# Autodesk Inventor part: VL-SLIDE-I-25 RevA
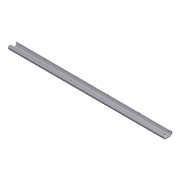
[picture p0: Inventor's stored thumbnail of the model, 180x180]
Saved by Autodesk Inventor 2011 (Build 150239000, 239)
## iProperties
Created: 2007-09
Part Number: VL-SLIDE-I-25 RevA
Material: Stainless Steel, Austenitic
Document SubType Name: Modeling
Density: 8.03 g/cm^3
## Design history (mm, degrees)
feature "Base1"
workplane "Work Plane1"
workplane "Work Plane2"
sketch "Sketch1" dims "d5" = 25.4
  geometry: L1 (0, 0)-(0, 10.16) reference; L2 (317.5, 0)-(0, 0) reference; L3 (317.5, 10.16)-(317.5, 0) reference; L4 (0, 10.16)-(317.5, 10.16) reference; L5 (296.647, 2.769)-(300.253, 2.769) reference; L6 (296.139, 6.883)-(296.139, 3.277) reference; L7 (300.253, 7.391)-(296.647, 7.391) reference; L8 (300.761, 3.277)-(300.761, 6.883) reference; L9 (283.947, 2.769)-(287.553, 2.769) reference; L10 (283.439, 6.883)-(283.439, 3.277) reference; L11 (287.553, 7.391)-(283.947, 7.391) reference; L12 (288.061, 3.277)-(288.061, 6.883) reference; L13 (271.247, 2.769)-(274.853, 2.769) reference; L14 (270.739, 6.883)-(270.739, 3.277) reference; L15 (274.853, 7.391)-(271.247, 7.391) reference; L16 (275.361, 3.277)-(275.361, 6.883) reference; L17 (258.547, 2.769)-(262.153, 2.769) reference; L18 (258.039, 6.883)-(258.039, 3.277) reference; L19 (262.153, 7.391)-(258.547, 7.391) reference; L20 (262.661, 3.277)-(262.661, 6.883) reference; L21 (245.847, 2.769)-(249.453, 2.769) reference; L22 (245.339, 6.883)-(245.339, 3.277) reference; L23 (249.453, 7.391)-(245.847, 7.391) reference; L24 (249.961, 3.277)-(249.961, 6.883) reference; L25 (233.147, 2.769)-(236.753, 2.769) reference; L26 (232.639, 6.883)-(232.639, 3.277) reference; L27 (236.753, 7.391)-(233.147, 7.391) reference; L28 (237.261, 3.277)-(237.261, 6.883) reference; L29 (220.447, 2.769)-(224.053, 2.769) reference; L30 (219.939, 6.883)-(219.939, 3.277) reference; L31 (224.053, 7.391)-(220.447, 7.391) reference; L32 (224.561, 3.277)-(224.561, 6.883) reference; L33 (207.747, 2.769)-(211.353, 2.769) reference; L34 (207.239, 6.883)-(207.239, 3.277) reference; L35 (211.353, 7.391)-(207.747, 7.391) reference; L36 (211.861, 3.277)-(211.861, 6.883) reference; L37 (195.047, 2.769)-(198.653, 2.769) reference; L38 (194.539, 6.883)-(194.539, 3.277) reference; L39 (198.653, 7.391)-(195.047, 7.391) reference; L40 (199.161, 3.277)-(199.161, 6.883) reference; L41 (182.347, 2.769)-(185.953, 2.769) reference; L42 (181.839, 6.883)-(181.839, 3.277) reference; L43 (185.953, 7.391)-(182.347, 7.391) reference; L44 (186.461, 3.277)-(186.461, 6.883) reference; L45 (169.647, 2.769)-(173.253, 2.769) reference; L46 (169.139, 6.883)-(169.139, 3.277) reference; L47 (173.253, 7.391)-(169.647, 7.391) reference; L48 (173.761, 3.277)-(173.761, 6.883) reference; L49 (156.947, 2.769)-(160.553, 2.769) reference; L50 (156.439, 6.883)-(156.439, 3.277) reference; L51 (160.553, 7.391)-(156.947, 7.391) reference; L52 (161.061, 3.277)-(161.061, 6.883) reference; L53 (144.247, 2.769)-(147.853, 2.769) reference; L54 (143.739, 6.883)-(143.739, 3.277) reference; L55 (147.853, 7.391)-(144.247, 7.391) reference; L56 (148.361, 3.277)-(148.361, 6.883) reference; L57 (131.547, 2.769)-(135.153, 2.769) reference; L58 (131.039, 6.883)-(131.039, 3.277) reference; L59 (135.153, 7.391)-(131.547, 7.391) reference; L60 (135.661, 3.277)-(135.661, 6.883) reference; L61 (118.847, 2.769)-(122.453, 2.769) reference; L62 (118.339, 6.883)-(118.339, 3.277) reference; L63 (122.453, 7.391)-(118.847, 7.391) reference; L64 (122.961, 3.277)-(122.961, 6.883) reference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; C1 r 2.311 at (6.35, 5.08); C2 r 2.311 at (19.05, 5.08); C3 r 2.311 at (31.75, 5.08); C4 r 2.311 at (44.45, 5.08); C5 r 2.311 at (57.15, 5.08); C6 r 2.311 at (69.85, 5.08); C7 r 2.311 at (82.55, 5.08); C8 r 2.311 at (95.25, 5.08); C9 r 2.311 at (107.95, 5.08); C10 r 2.311 at (120.65, 5.08); C11 r 2.311 at (133.35, 5.08); C12 r 2.311 at (146.05, 5.08); C13 r 2.311 at (158.75, 5.08); C14 r 2.311 at (171.45, 5.08); C15 r 2.311 at (184.15, 5.08); C16 r 2.311 at (196.85, 5.08); C17 r 2.311 at (209.55, 5.08); C18 r 2.311 at (222.25, 5.08); C19 r 2.311 at (234.95, 5.08); C20 r 2.311 at (247.65, 5.08); C21 r 2.311 at (260.35, 5.08); C22 r 2.311 at (273.05, 5.08); C23 r 2.311 at (285.75, 5.08); C24 r 2.311 at (298.45, 5.08); C25 r 2.311 at (311.15, 5.08); A1 r 0.508 centre (296.647, 3.277) between (296.139, 3.277) and (296.647, 2.769) reference; A2 r 0.508 centre (296.647, 6.883) between (296.647, 7.391) and (296.139, 6.883) reference; A3 r 0.508 centre (300.253, 6.883) between (300.761, 6.883) and (300.253, 7.391) reference; A4 r 0.508 centre (300.253, 3.277) between (300.253, 2.769) and (300.761, 3.277) reference; A5 r 0.508 centre (283.947, 3.277) between (283.439, 3.277) and (283.947, 2.769) reference; A6 r 0.508 centre (283.947, 6.883) between (283.947, 7.391) and (283.439, 6.883) reference; A7 r 0.508 centre (287.553, 6.883) between (288.061, 6.883) and (287.553, 7.391) reference; A8 r 0.508 centre (287.553, 3.277) between (287.553, 2.769) and (288.061, 3.277) reference; A9 r 0.508 centre (271.247, 3.277) between (270.739, 3.277) and (271.247, 2.769) reference; A10 r 0.508 centre (271.247, 6.883) between (271.247, 7.391) and (270.739, 6.883) reference; A11 r 0.508 centre (274.853, 6.883) between (275.361, 6.883) and (274.853, 7.391) reference; A12 r 0.508 centre (274.853, 3.277) between (274.853, 2.769) and (275.361, 3.277) reference; A13 r 0.508 centre (258.547, 3.277) between (258.039, 3.277) and (258.547, 2.769) reference; A14 r 0.508 centre (258.547, 6.883) between (258.547, 7.391) and (258.039, 6.883) reference; A15 r 0.508 centre (262.153, 6.883) between (262.661, 6.883) and (262.153, 7.391) reference; A16 r 0.508 centre (262.153, 3.277) between (262.153, 2.769) and (262.661, 3.277) reference; A17 r 0.508 centre (245.847, 3.277) between (245.339, 3.277) and (245.847, 2.769) reference; A18 r 0.508 centre (245.847, 6.883) between (245.847, 7.391) and (245.339, 6.883) reference; A19 r 0.508 centre (249.453, 6.883) between (249.961, 6.883) and (249.453, 7.391) reference; A20 r 0.508 centre (249.453, 3.277) between (249.453, 2.769) and (249.961, 3.277) reference; A21 r 0.508 centre (233.147, 3.277) between (232.639, 3.277) and (233.147, 2.769) reference; A22 r 0.508 centre (233.147, 6.883) between (233.147, 7.391) and (232.639, 6.883) reference; A23 r 0.508 centre (236.753, 6.883) between (237.261, 6.883) and (236.753, 7.391) reference; A24 r 0.508 centre (236.753, 3.277) between (236.753, 2.769) and (237.261, 3.277) reference; A25 r 0.508 centre (220.447, 3.277) between (219.939, 3.277) and (220.447, 2.769) reference; A26 r 0.508 centre (220.447, 6.883) between (220.447, 7.391) and (219.939, 6.883) reference; A27 r 0.508 centre (224.053, 6.883) between (224.561, 6.883) and (224.053, 7.391) reference; A28 r 0.508 centre (224.053, 3.277) between (224.053, 2.769) and (224.561, 3.277) reference; A29 r 0.508 centre (207.747, 3.277) between (207.239, 3.277) and (207.747, 2.769) reference; A30 r 0.508 centre (207.747, 6.883) between (207.747, 7.391) and (207.239, 6.883) reference; A31 r 0.508 centre (211.353, 6.883) between (211.861, 6.883) and (211.353, 7.391) reference; A32 r 0.508 centre (211.353, 3.277) between (211.353, 2.769) and (211.861, 3.277) reference; A33 r 0.508 centre (195.047, 3.277) between (194.539, 3.277) and (195.047, 2.769) reference; A34 r 0.508 centre (195.047, 6.883) between (195.047, 7.391) and (194.539, 6.883) reference; A35 r 0.508 centre (198.653, 6.883) between (199.161, 6.883) and (198.653, 7.391) reference; A36 r 0.508 centre (198.653, 3.277) between (198.653, 2.769) and (199.161, 3.277) reference; A37 r 0.508 centre (182.347, 3.277) between (181.839, 3.277) and (182.347, 2.769) reference; A38 r 0.508 centre (182.347, 6.883) between (182.347, 7.391) and (181.839, 6.883) reference; A39 r 0.508 centre (185.953, 6.883) between (186.461, 6.883) and (185.953, 7.391) reference; A40 r 0.508 centre (185.953, 3.277) between (185.953, 2.769) and (186.461, 3.277) reference; A41 r 0.508 centre (169.647, 3.277) between (169.139, 3.277) and (169.647, 2.769) reference; A42 r 0.508 centre (169.647, 6.883) between (169.647, 7.391) and (169.139, 6.883) reference; A43 r 0.508 centre (173.253, 6.883) between (173.761, 6.883) and (173.253, 7.391) reference; A44 r 0.508 centre (173.253, 3.277) between (173.253, 2.769) and (173.761, 3.277) reference; A45 r 0.508 centre (156.947, 3.277) between (156.439, 3.277) and (156.947, 2.769) reference; A46 r 0.508 centre (156.947, 6.883) between (156.947, 7.391) and (156.439, 6.883) reference; A47 r 0.508 centre (160.553, 6.883) between (161.061, 6.883) and (160.553, 7.391) reference; A48 r 0.508 centre (160.553, 3.277) between (160.553, 2.769) and (161.061, 3.277) reference; A49 r 0.508 centre (144.247, 3.277) between (143.739, 3.277) and (144.247, 2.769) reference; A50 r 0.508 centre (144.247, 6.883) between (144.247, 7.391) and (143.739, 6.883) reference; A51 r 0.508 centre (147.853, 6.883) between (148.361, 6.883) and (147.853, 7.391) reference; A52 r 0.508 centre (147.853, 3.277) between (147.853, 2.769) and (148.361, 3.277) reference; A53 r 0.508 centre (131.547, 3.277) between (131.039, 3.277) and (131.547, 2.769) reference; A54 r 0.508 centre (131.547, 6.883) between (131.547, 7.391) and (131.039, 6.883) reference; A55 r 0.508 centre (135.153, 6.883) between (135.661, 6.883) and (135.153, 7.391) reference; A56 r 0.508 centre (135.153, 3.277) between (135.153, 2.769) and (135.661, 3.277) reference; A57 r 0.508 centre (118.847, 3.277) between (118.339, 3.277) and (118.847, 2.769) reference; A58 r 0.508 centre (118.847, 6.883) between (118.847, 7.391) and (118.339, 6.883) reference; A59 r 0.508 centre (122.453, 6.883) between (122.961, 6.883) and (122.453, 7.391) reference; A60 r 0.508 centre (122.453, 3.277) between (122.453, 2.769) and (122.961, 3.277) reference; A61 r 0.508 centre (106.147, 3.277) between (105.639, 3.277) and (106.147, 2.769) reference; A62 r 0.508 centre (106.147, 6.883) between (106.147, 7.391) and (105.639, 6.883) reference; A63 r 0.508 centre (109.753, 6.883) between (110.261, 6.883) and (109.753, 7.391) reference; A64 r 0.508 centre (109.753, 3.277) between (109.753, 2.769) and (110.261, 3.277) reference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
  constraints: 25 centre point, 4 tangent, 1 horizontal, 48 other
  dimensions: "d2" = 12.7 distance of C1.centre C2.centre
body "Solid1"
